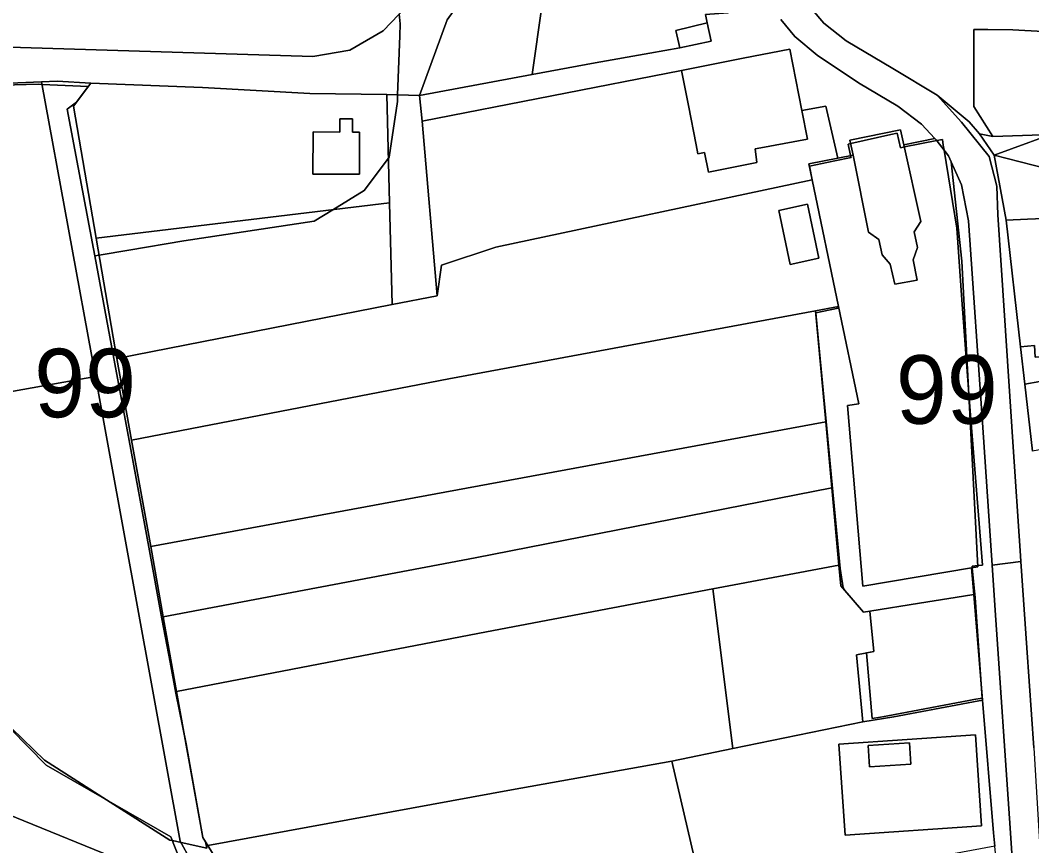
# Model space of a CAD drawing. Extents: x -522079 to -518792, y -1142400 to -1139961.
# Drawn here: x -520504.8 to -520283.3, y -1141353.9 to -1141173.1 of the extents above; entities that cross this region are included whole.
import ezdxf

# ---------------------------------------------------------------- set-up
doc = ezdxf.new("R2010")
doc.units = 0
for name, color, linetype in [('Hranice parcel', 7, 'Continuous'), ('Parcelní čísla', 7, 'Continuous'), ('Poz předměty', 7, 'Continuous'), ('Vnitřní kresba', 7, 'Continuous'), ('Značky bodu BP', 7, 'Continuous'), ('Značky kultur', 7, 'Continuous')]:
    doc.layers.add(name, color=color, linetype=linetype)

msp = doc.modelspace()

# ---------------------------------------------------------------- linework, layer by layer
at = {"layer": 'Hranice parcel'}
for points in [[(-520417.36, -1141189.63), (-520392.71, -1141184.99), (-520378.86, -1141182.41), (-520366.93, -1141180.34), (-520360.34, -1141179.18), (-520353.47, -1141177.71), (-520354.34, -1141173.71), (-520354.71, -1141171.83), (-520349.86, -1141171.48), (-520346.65, -1141169.3), (-520347.81, -1141152.92), (-520347.61, -1141152.91), (-520349.11, -1141131.64), (-520357.95, -1141132.21), (-520359.15, -1141132.28), (-520370.32, -1141133), (-520379.87, -1141135.97), (-520380.82, -1141136.27), (-520393.37, -1141144.49), (-520399.1, -1141160.34), (-520402.63, -1141160.92), (-520411.3, -1141173.03)], [(-520354.34, -1141173.71), (-520353.47, -1141177.71), (-520360.34, -1141179.18), (-520361.25, -1141175.35)], [(-520291.52, -1141202.69), (-520294.74, -1141198), (-520291.83, -1141198.59), (-520280.99, -1141198.2), (-520276.81, -1141192.82), (-520265.75, -1141173.55), (-520262.34, -1141173.28), (-520263.7, -1141175.46), (-520265.8, -1141179.08), (-520267.83, -1141182.58), (-520270.74, -1141187.55), (-520275.56, -1141196.82)], [(-520287.4, -1141175.25), (-520284.8, -1141175.38), (-520276.61, -1141175.8), (-520273.02, -1141178.12), (-520276.81, -1141192.82), (-520280.99, -1141198.2), (-520291.83, -1141198.59), (-520295.98, -1141192.02), (-520296.01, -1141175.11), (-520292.9, -1141175.16)], [(-520336.24, -1141179.42), (-520333.6, -1141192.88), (-520332.37, -1141199.14), (-520342.6, -1141201.05), (-520343.86, -1141201.29), (-520343.47, -1141204.29), (-520354.06, -1141206.38), (-520354.91, -1141202.07), (-520356.39, -1141202.36), (-520356.77, -1141200.4), (-520358.48, -1141191.76), (-520359.99, -1141184.11), (-520346.46, -1141181.44)], [(-520535.7, -1141238.47), (-520524.27, -1141187.6), (-520500.08, -1141186.63), (-520488.31, -1141251.1), (-520534.84, -1141259.42), (-520534.05, -1141249.88)], [(-520432.03, -1141197.59), (-520430.48, -1141197.6), (-520430.51, -1141206.85), (-520440.68, -1141206.8), (-520440.66, -1141197.58), (-520434.81, -1141197.59), (-520434.8, -1141194.69), (-520432, -1141194.68)], [(-520309.23, -1141225.55), (-520308.37, -1141230.04), (-520313.3, -1141230.91), (-520314.28, -1141226.51), (-520316.06, -1141224.47), (-520316.76, -1141221.12), (-520319.07, -1141219.54), (-520322.39, -1141202.63), (-520323.1, -1141199.37), (-520312, -1141197.1), (-520311.28, -1141200.4), (-520307.6, -1141217.21), (-520309.05, -1141219.45), (-520308.34, -1141222.91)], [(-520275.56, -1141196.82), (-520280.13, -1141205.59), (-520291.52, -1141202.69)], [(-520323.62, -1141257.49), (-520321.16, -1141257.11), (-520325.59, -1141235.8), (-520331.36, -1141208.07), (-520332.09, -1141204.58), (-520325.76, -1141203.31), (-520322.39, -1141202.63), (-520319.07, -1141219.54), (-520316.76, -1141221.12), (-520316.06, -1141224.47), (-520314.28, -1141226.51), (-520313.3, -1141230.91), (-520308.37, -1141230.04), (-520309.23, -1141225.55), (-520308.34, -1141222.91), (-520309.05, -1141219.45), (-520307.6, -1141217.21), (-520311.28, -1141200.4), (-520304.49, -1141199.02), (-520304.21, -1141199.32), (-520301.55, -1141202.8), (-520300.95, -1141204.15), (-520298.61, -1141225.85), (-520295.11, -1141292.82), (-520296.48, -1141293.05), (-520320.29, -1141297.03)], [(-520285.62, -1141431.18), (-520287.2, -1141396.11), (-520288.69, -1141381.19), (-520291.41, -1141353.94), (-520291.7, -1141351.03), (-520294.09, -1141322.02), (-520296, -1141298.82), (-520296.48, -1141293.05), (-520295.11, -1141292.82), (-520298.61, -1141225.85), (-520300.95, -1141204.15), (-520298.67, -1141209.18), (-520297.11, -1141217.05), (-520293.97, -1141262.32), (-520291.98, -1141292.42), (-520291.26, -1141303.35), (-520288.07, -1141348.91), (-520285.88, -1141381.79), (-520283.95, -1141411.07), (-520283.46, -1141431.12)], [(-520336.17, -1141226.59), (-520338.66, -1141214.74), (-520332.41, -1141213.42), (-520329.89, -1141225.22)], [(-520252.29, -1141220.01), (-520254.68, -1141219.42), (-520253.52, -1141236.33), (-520253.62, -1141239.61), (-520274.53, -1141243.54), (-520278.18, -1141243.9), (-520278.03, -1141246.64), (-520282.52, -1141246.89), (-520282.66, -1141244.34), (-520285.74, -1141244.64), (-520288.93, -1141216.9), (-520284.22, -1141216.65), (-520265.11, -1141215.87), (-520258.35, -1141216.74), (-520252.46, -1141217.61)], [(-520323.62, -1141257.49), (-520320.29, -1141297.03), (-520296.48, -1141293.05), (-520296, -1141298.82), (-520298.25, -1141299.19), (-520307.88, -1141300.74), (-520318.74, -1141302.49), (-520320.11, -1141302.71), (-520325.09, -1141296.95), (-520325.5, -1141292.44), (-520327.05, -1141275.53), (-520328.39, -1141261.02), (-520330.62, -1141236.74), (-520325.59, -1141235.8), (-520321.16, -1141257.11)], [(-520253.23, -1141262.13), (-520266.64, -1141264.52), (-520278.73, -1141266.68), (-520283.12, -1141267.46), (-520284.8, -1141252.79), (-520281.5, -1141252.18), (-520269.34, -1141249.93), (-520252.79, -1141247.01), (-520250.1, -1141261.57)], [(-520321.67, -1141312.05), (-520317.9, -1141311.37), (-520318.74, -1141302.49), (-520307.88, -1141300.74), (-520298.25, -1141299.19), (-520296, -1141298.82), (-520294.09, -1141322.02), (-520296.08, -1141322.39), (-520313.48, -1141325.64), (-520320.3, -1141326.77)], [(-520325.53, -1141331.62), (-520295.63, -1141329.58), (-520294.28, -1141349.48), (-520324.17, -1141351.52)], [(-520310.06, -1141331.33), (-520319.11, -1141331.93), (-520318.81, -1141336.57), (-520309.76, -1141335.98)], [(-520309.76, -1141335.98), (-520318.81, -1141336.57), (-520319.11, -1141331.93), (-520310.06, -1141331.33)]]:
    msp.add_lwpolyline(points, close=True, dxfattribs=at)
for points in [[(-520523.78, -1141178.47), (-520440.68, -1141181.04), (-520432.59, -1141179.7), (-520425.27, -1141175.41), (-520408.18, -1141157.48)], [(-520333.5, -1141168.21), (-520328.85, -1141173.77), (-520323.9, -1141177.63), (-520313.7, -1141183.68), (-520304, -1141189.53), (-520298.66, -1141195.42), (-520292.63, -1141202.98), (-520290.93, -1141209.43), (-520290.72, -1141215.76), (-520289.28, -1141237.74), (-520287.43, -1141265.4), (-520285.78, -1141290.4), (-520285.69, -1141291.6), (-520291.98, -1141292.42), (-520293.97, -1141262.32), (-520297.11, -1141217.05), (-520298.67, -1141209.18), (-520300.95, -1141204.15), (-520301.55, -1141202.8), (-520304.21, -1141199.32), (-520304.49, -1141199.02), (-520307.43, -1141195.9), (-520312.59, -1141191.95), (-520321.21, -1141186.85), (-520330.27, -1141180.78), (-520335.19, -1141176.69), (-520338.22, -1141172.95)], [(-520263.33, -1141170.08), (-520262.34, -1141173.28), (-520265.75, -1141173.55), (-520276.61, -1141175.8), (-520284.8, -1141175.38), (-520287.4, -1141175.25), (-520292.9, -1141175.16), (-520296.01, -1141175.11), (-520295.98, -1141192.02), (-520291.83, -1141198.59), (-520294.74, -1141198), (-520297.02, -1141195.35), (-520304, -1141189.53), (-520313.7, -1141183.68), (-520323.9, -1141177.63), (-520328.85, -1141173.77), (-520333.5, -1141168.21)], [(-520338.22, -1141172.95), (-520335.19, -1141176.69), (-520330.27, -1141180.78), (-520321.21, -1141186.85), (-520312.59, -1141191.95), (-520307.43, -1141195.9), (-520304.49, -1141199.02), (-520311.28, -1141200.4), (-520312, -1141197.1), (-520323.1, -1141199.37), (-520322.39, -1141202.63), (-520325.76, -1141203.31), (-520328.4, -1141191.92), (-520333.6, -1141192.88), (-520336.24, -1141179.42), (-520346.46, -1141181.44), (-520359.99, -1141184.11), (-520416.76, -1141195.21), (-520417.36, -1141189.63), (-520424.53, -1141189.37), (-520441.37, -1141189.15), (-520464.88, -1141187.85), (-520489.31, -1141186.91), (-520496.7, -1141186.49), (-520500.08, -1141186.63), (-520524.27, -1141187.6)], [(-520465.21, -1141361), (-520469.72, -1141352.88), (-520488.31, -1141251.1), (-520500.08, -1141186.63), (-520496.7, -1141186.49), (-520489.31, -1141186.91), (-520493.12, -1141191.96), (-520488.14, -1141220.84), (-520483.58, -1141247.19), (-520480.37, -1141265.08), (-520476.2, -1141288.34), (-520473.45, -1141303.71), (-520470.52, -1141320.08), (-520464.8, -1141352.03), (-520463.71, -1141353.8), (-520460.62, -1141358.83)], [(-520282.86, -1141332.45), (-520284.36, -1141310.52), (-520285.69, -1141291.6), (-520285.78, -1141290.4), (-520287.43, -1141265.4), (-520289.28, -1141237.74), (-520290.72, -1141215.76), (-520290.93, -1141209.43), (-520292.63, -1141202.98), (-520298.66, -1141195.42), (-520304, -1141189.53), (-520297.02, -1141195.35), (-520294.74, -1141198), (-520291.52, -1141202.69), (-520288.93, -1141216.9), (-520285.74, -1141244.64), (-520284.8, -1141252.79), (-520283.12, -1141267.46)], [(-520265.11, -1141215.87), (-520284.22, -1141216.65), (-520288.93, -1141216.9), (-520291.52, -1141202.69), (-520280.13, -1141205.59)], [(-520290.19, -1141514.57), (-520288.42, -1141473.23), (-520287.25, -1141456.97), (-520285.53, -1141433.12), (-520285.62, -1141431.18), (-520283.46, -1141431.12), (-520283.95, -1141411.07), (-520285.88, -1141381.79), (-520288.07, -1141348.91), (-520291.26, -1141303.35), (-520291.98, -1141292.42), (-520285.69, -1141291.6), (-520284.36, -1141310.52), (-520282.86, -1141332.45), (-520281.66, -1141351.81), (-520280.36, -1141370.5), (-520279.11, -1141388.58), (-520278.27, -1141410.62), (-520277.86, -1141423.4), (-520277.92, -1141430.99), (-520274.48, -1141431.01), (-520274.69, -1141472.35), (-520275.67, -1141487.93), (-520277.2, -1141512.43)]]:
    msp.add_lwpolyline(points, dxfattribs=at)
at = {"layer": 'Parcelní čísla'}
for points in [[(-520400.61, -1141222.82), (-520331.36, -1141208.07), (-520325.59, -1141235.8), (-520330.62, -1141236.74), (-520410.93, -1141251.63), (-520480.37, -1141265.08), (-520483.58, -1141247.19), (-520423.33, -1141235.38), (-520413.51, -1141233.43), (-520412.54, -1141226.76)], [(-520423.33, -1141235.38), (-520483.58, -1141247.19), (-520488.14, -1141220.84), (-520423.9, -1141213.13)], [(-520336.17, -1141226.59), (-520329.89, -1141225.22), (-520332.41, -1141213.42), (-520338.66, -1141214.74)], [(-520330.62, -1141236.74), (-520328.39, -1141261.02), (-520407.05, -1141275.59), (-520476.2, -1141288.34), (-520480.37, -1141265.08), (-520410.93, -1141251.63)], [(-520476.2, -1141288.34), (-520407.05, -1141275.59), (-520328.39, -1141261.02), (-520327.05, -1141275.53), (-520405.18, -1141290.79), (-520473.45, -1141303.71)], [(-520405.18, -1141290.79), (-520327.05, -1141275.53), (-520325.5, -1141292.44), (-520353.1, -1141297.63), (-520402.69, -1141307.02), (-520470.52, -1141320.08), (-520473.45, -1141303.71)], [(-520353.1, -1141297.63), (-520348.74, -1141332.58), (-520362.13, -1141335.31), (-520397.21, -1141341.61), (-520463.71, -1141353.8), (-520464.8, -1141352.03), (-520470.52, -1141320.08), (-520402.69, -1141307.02)], [(-520368.84, -1141368.35), (-520378.01, -1141370.07), (-520457.31, -1141385.57), (-520460.62, -1141358.83), (-520463.71, -1141353.8), (-520397.21, -1141341.61), (-520362.13, -1141335.31), (-520355.94, -1141361.7), (-520369.53, -1141364.42)]]:
    msp.add_lwpolyline(points, close=True, dxfattribs=at)
at = {"layer": 'Poz předměty'}
for points in [[(-520432.59, -1141179.7), (-520440.68, -1141181.04), (-520523.78, -1141178.47), (-520526.48, -1141178.44), (-520526.38, -1141166.45), (-520421.91, -1141158.52), (-520408.18, -1141157.48), (-520425.27, -1141175.41)], [(-520534.35, -1141283.17), (-520535.3, -1141264.93), (-520534.84, -1141259.42), (-520488.31, -1141251.1), (-520469.72, -1141352.88), (-520465.21, -1141361), (-520463.1, -1141373.93), (-520471.76, -1141351.9), (-520499.06, -1141336.21), (-520518.61, -1141316.36), (-520539.2, -1141310.09)], [(-520474.23, -1141423.42), (-520512.06, -1141431.3), (-520564.35, -1141443.41), (-520567.96, -1141415.92), (-520573.91, -1141353.97), (-520575.29, -1141345.21), (-520582.4, -1141266.58), (-520545.37, -1141264.63), (-520546.39, -1141287.04), (-520556.25, -1141307.68), (-520549.32, -1141316.76), (-520521.95, -1141327.46), (-520517.94, -1141333.55), (-520509.58, -1141346.13), (-520479.06, -1141358.55)]]:
    msp.add_lwpolyline(points, close=True, dxfattribs=at)
at = {"layer": 'Vnitřní kresba'}
for points in [[(-520518.61, -1141316.36), (-520499.06, -1141336.21), (-520471.76, -1141351.9), (-520463.1, -1141373.93), (-520462.06, -1141386.7), (-520456.11, -1141417.28), (-520459.35, -1141430.33), (-520501.13, -1141439.65), (-520485.81, -1141474.99), (-520499.43, -1141490.33), (-520494.54, -1141511.04)], [(-520512.06, -1141431.3), (-520474.23, -1141423.42), (-520479.06, -1141358.55), (-520509.58, -1141346.13)]]:
    msp.add_lwpolyline(points, dxfattribs=at)
at = {"layer": 'Značky bodu BP'}
for points in [[(-520421.78, -1141171.75), (-520421.57, -1141173.87), (-520421.67, -1141176.52), (-520422.13, -1141189.45), (-520422.18, -1141190.93), (-520424, -1141203.11), (-520424.16, -1141203.33), (-520429.47, -1141210.43), (-520436.3, -1141214.61), (-520440.4, -1141217.13), (-520468.94, -1141221.4), (-520481.02, -1141223.43), (-520487.5, -1141224.52), (-520488.45, -1141224.68), (-520488.74, -1141223.16), (-520494.47, -1141192.6), (-520492.42, -1141191.02), (-520489.87, -1141187.64), (-520499.98, -1141187.16), (-520500.85, -1141187.11), (-520524.31, -1141187.79)], [(-520463.9, -1141354.41), (-520464.18, -1141353.04), (-520464.8, -1141352.03), (-520468.46, -1141331.58), (-520470.68, -1141320.48), (-520471.96, -1141313.67), (-520473.73, -1141304.21), (-520476.59, -1141288.49), (-520480.92, -1141265.11), (-520484.03, -1141248.32), (-520488.45, -1141224.68), (-520487.5, -1141224.52), (-520481.02, -1141223.43), (-520468.94, -1141221.4), (-520440.4, -1141217.13), (-520436.3, -1141214.61), (-520429.47, -1141210.43), (-520424.16, -1141203.33), (-520424, -1141203.11), (-520422.18, -1141190.93), (-520422.13, -1141189.45), (-520421.67, -1141176.52), (-520421.57, -1141173.87), (-520421.78, -1141171.75)], [(-520524.31, -1141187.79), (-520500.85, -1141187.11), (-520499.98, -1141187.16), (-520489.87, -1141187.64), (-520492.42, -1141191.02), (-520494.47, -1141192.6), (-520488.74, -1141223.16), (-520488.45, -1141224.68), (-520484.03, -1141248.32), (-520480.92, -1141265.11), (-520476.59, -1141288.49), (-520473.73, -1141304.21), (-520471.96, -1141313.67), (-520470.68, -1141320.48), (-520468.46, -1141331.58), (-520464.8, -1141352.03), (-520464.18, -1141353.04), (-520463.9, -1141354.41), (-520469.56, -1141353.16), (-520471.42, -1141352.75), (-520472, -1141352.62), (-520485.86, -1141343.79), (-520499.45, -1141335.14), (-520511.59, -1141323.48)], [(-520511.59, -1141323.48), (-520499.45, -1141335.14), (-520485.86, -1141343.79), (-520472, -1141352.62), (-520471.42, -1141352.75), (-520469.56, -1141353.16), (-520463.9, -1141354.41)]]:
    msp.add_lwpolyline(points, dxfattribs=at)
for points in [[(-520324.21, -1141297.97), (-520320.11, -1141302.71), (-520318.74, -1141302.49), (-520317.9, -1141311.37), (-520319.44, -1141311.65), (-520318.26, -1141326.04), (-520316.42, -1141325.7), (-520314.79, -1141325.4), (-520297.05, -1141322.07), (-520295.96, -1141321.86), (-520294.14, -1141321.52), (-520294.21, -1141320.54), (-520295.03, -1141308.97), (-520295.71, -1141299.5), (-520295.98, -1141296.72), (-520296.33, -1141293.02), (-520296.37, -1141292.63), (-520295.12, -1141292.53), (-520294.1, -1141292.44), (-520296.65, -1141260.49), (-520297.09, -1141254.93), (-520297.17, -1141253.88), (-520298.58, -1141234.31), (-520299.7, -1141218.66), (-520302.48, -1141201.59), (-520302.66, -1141200.45), (-520302.86, -1141199.2), (-520304.11, -1141199.45), (-520311.18, -1141200.87), (-520312.03, -1141201.04), (-520312.79, -1141197.82), (-520314.17, -1141198.13), (-520322.93, -1141200.13), (-520323.52, -1141200.27), (-520322.95, -1141202.74), (-520322.84, -1141203.2), (-520326.41, -1141203.92), (-520331.99, -1141205.04), (-520331.36, -1141208.07), (-520325.59, -1141235.8), (-520325.73, -1141235.83), (-520325.66, -1141236.16), (-520330.58, -1141237.17), (-520329.94, -1141244.17), (-520328.29, -1141261.01), (-520326.88, -1141276.37), (-520325.24, -1141293.13), (-520324.61, -1141297.39)], [(-520312.79, -1141197.82), (-520312.03, -1141201.04), (-520311.18, -1141200.87), (-520304.11, -1141199.45), (-520302.86, -1141199.2), (-520302.66, -1141200.45), (-520302.48, -1141201.59), (-520299.7, -1141218.66), (-520298.58, -1141234.31), (-520297.17, -1141253.88), (-520297.09, -1141254.93), (-520296.65, -1141260.49), (-520294.1, -1141292.44), (-520295.12, -1141292.53), (-520296.37, -1141292.63), (-520296.33, -1141293.02), (-520295.98, -1141296.72), (-520295.71, -1141299.5), (-520295.03, -1141308.97), (-520294.21, -1141320.54), (-520294.14, -1141321.52), (-520295.96, -1141321.86), (-520297.05, -1141322.07), (-520314.79, -1141325.4), (-520316.42, -1141325.7), (-520318.26, -1141326.04), (-520319.44, -1141311.65), (-520317.9, -1141311.37), (-520318.74, -1141302.49), (-520320.11, -1141302.71), (-520324.21, -1141297.97), (-520324.61, -1141297.39), (-520325.24, -1141293.13), (-520326.88, -1141276.37), (-520328.29, -1141261.01), (-520329.94, -1141244.17), (-520330.58, -1141237.17), (-520325.66, -1141236.16), (-520325.73, -1141235.83), (-520325.59, -1141235.8), (-520331.36, -1141208.07), (-520331.99, -1141205.04), (-520326.41, -1141203.92), (-520322.84, -1141203.2), (-520322.95, -1141202.74), (-520323.52, -1141200.27), (-520322.93, -1141200.13), (-520314.17, -1141198.13)]]:
    msp.add_lwpolyline(points, close=True, dxfattribs=at)
at = {"layer": 'Značky kultur'}
for points in [[(-520392.71, -1141184.99), (-520390.51, -1141169.6), (-520385.67, -1141162.39), (-520383.02, -1141163.15), (-520382.54, -1141163.3), (-520381.05, -1141158.47), (-520376.18, -1141142.7), (-520369.8, -1141141.08), (-520369.36, -1141147.79), (-520364.41, -1141148.17), (-520363.98, -1141154.29), (-520356.57, -1141153.77), (-520356.59, -1141153.47), (-520347.81, -1141152.92), (-520346.65, -1141169.3), (-520349.86, -1141171.48), (-520354.71, -1141171.83), (-520354.34, -1141173.71), (-520361.25, -1141175.35), (-520360.34, -1141179.18), (-520366.93, -1141180.34), (-520378.86, -1141182.41)], [(-520417.36, -1141189.63), (-520411.3, -1141173.03), (-520402.63, -1141160.92), (-520399.1, -1141160.34), (-520393.37, -1141144.49), (-520399.12, -1141167.44), (-520392.92, -1141168.99), (-520390.51, -1141169.6), (-520392.71, -1141184.99)], [(-520358.48, -1141191.76), (-520356.77, -1141200.4), (-520356.39, -1141202.36), (-520354.91, -1141202.07), (-520354.06, -1141206.38), (-520343.47, -1141204.29), (-520343.86, -1141201.29), (-520342.6, -1141201.05), (-520332.37, -1141199.14), (-520333.6, -1141192.88), (-520328.4, -1141191.92), (-520325.76, -1141203.31), (-520332.09, -1141204.58), (-520331.36, -1141208.07), (-520400.61, -1141222.82), (-520412.54, -1141226.76), (-520413.51, -1141233.43), (-520416.76, -1141195.21), (-520359.99, -1141184.11)], [(-520493.12, -1141191.96), (-520489.31, -1141186.91), (-520464.88, -1141187.85), (-520441.37, -1141189.15), (-520424.53, -1141189.37), (-520423.9, -1141213.13), (-520488.14, -1141220.84)], [(-520423.33, -1141235.38), (-520423.9, -1141213.13), (-520424.53, -1141189.37), (-520417.36, -1141189.63), (-520416.76, -1141195.21), (-520413.51, -1141233.43)], [(-520432.03, -1141197.59), (-520432, -1141194.68), (-520434.8, -1141194.69), (-520434.81, -1141197.59), (-520440.66, -1141197.58), (-520440.68, -1141206.8), (-520430.51, -1141206.85), (-520430.48, -1141197.6)], [(-520281.5, -1141252.18), (-520284.8, -1141252.79), (-520285.74, -1141244.64), (-520282.66, -1141244.34), (-520282.52, -1141246.89), (-520278.03, -1141246.64), (-520278.18, -1141243.9), (-520274.53, -1141243.54), (-520253.62, -1141239.61), (-520253.52, -1141236.33), (-520252.79, -1141247.01), (-520269.34, -1141249.93)], [(-520325.09, -1141296.95), (-520320.11, -1141302.71), (-520318.74, -1141302.49), (-520317.9, -1141311.37), (-520321.67, -1141312.05), (-520320.3, -1141326.77), (-520348.74, -1141332.58), (-520353.1, -1141297.63), (-520325.5, -1141292.44)], [(-520355.94, -1141361.7), (-520362.13, -1141335.31), (-520348.74, -1141332.58), (-520320.3, -1141326.77), (-520313.48, -1141325.64), (-520296.08, -1141322.39), (-520294.09, -1141322.02), (-520291.7, -1141351.03), (-520291.41, -1141353.94), (-520322.8, -1141359.78), (-520368.84, -1141368.35), (-520369.53, -1141364.42)], [(-520295.63, -1141329.58), (-520325.53, -1141331.62), (-520324.17, -1141351.52), (-520294.28, -1141349.48)]]:
    msp.add_lwpolyline(points, close=True, dxfattribs=at)

# ---------------------------------------------------------------- texts
at = {"layer": 'Značky bodu BP'}
for rotation, p in [(0, (-520501.71, -1141260.05)), (360, (-520313.04, -1141261.47))]:
    msp.add_text('99', height=15, rotation=rotation, dxfattribs=at).set_placement(p)

doc.saveas('drawing.dxf')
